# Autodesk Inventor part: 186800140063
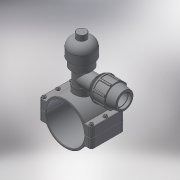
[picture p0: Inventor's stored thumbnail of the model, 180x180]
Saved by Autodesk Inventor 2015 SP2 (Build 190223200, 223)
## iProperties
Created: 2017-05
Part Number: 186800140063
Material: Generic
Description: PLASSON MECHANICAL TAPPING VALVE 140-63
Document SubType Name: Modeling
Designer: KIM
Density: 1 g/cm^3
Appearance: Default
Author: KIM
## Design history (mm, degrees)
derived "18680.ipt"
feature "Solid1::18680.ipt"
feature "Solid2::18680.ipt"
tag "TaggingFeature1"
body "Solid1"
other parameters: "d0" = 154, "d1" = 201, "d4" = 136, "d5" = 0, "d6" = 10.05, "d7" = 201, "d8" = 0.1, "d10" = 0, "d11" = 1.4, "d14" = 73.6528, "d20" = 1.4, "d23" = 1.4, "d36" = 15, "d37" = 12, "d38" = 78, "d39" = 0, "d40" = 3, "d41" = 5, "d42" = 0, "d44" = 3, "d45" = 0, "d46" = 1.4, "d51" = 101, "d52" = 56.656, "d53" = 21, "d54" = 0, "d57" = 0, "d58" = 151.2, "d60" = 0, "d62" = 15, "d63" = 12, "d66" = 112, "d67" = 63, "d68" = 16.66667, "d70" = 113, "d71" = 84.75, "d72" = 2.85714, "d73" = 90.4, "d74" = 120 deg, "d75" = 81.9, "d76" = 10 deg, "d77" = 101.7, "d80" = 50.4, "d82" = 11, "d87" = 28.57143, "d90" = 105.09, "d91" = 35 deg, "d92" = 17.5 deg, "d94" = 0, "d96" = 360 deg, "d98" = 1.26, "d99" = 121, "d100" = 67.8, "d101" = 135 deg, "d102" = 2.26, "d105" = 5.65, "d106" = 0, "d107" = 0.1, "d109" = 73.6528, "d112" = 34.85714, "d113" = 6.66667, "d116" = 0, "d121" = 67.9872, "d122" = 113.312, "d123" = 96.3152, "d124" = 45 deg, "d125" = 219.6, "d126" = 244, "d127" = 146.4, "d128" = 1, "d129" = 65, "G_" = 56.656, "A_" = 101, "L_" = 201, "L_1" = 136, "l_2" = 21, "d_1" = 63, "E_" = 113, "H_1" = 65, "H_2" = 244
